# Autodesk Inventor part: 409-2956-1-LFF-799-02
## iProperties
Created: 2010-11
Part Number: 409-2956-1-LFF-799-02
Material: 3/4" OD TUBE - SS
Document SubType Name: Modeling
Designer: S. Boerckel
Engineer: Steve Boerckel
Mass: 309.983 g
Surface Area: 466.545 cm^2
Volume: 38.3643 cm^3
Density: 8.08 g/cm^3
Description: DRAIN TUBING
Length: 22.316 in
Author: S. Boerckel
Revision Number: 0
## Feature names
1. Sweep1
